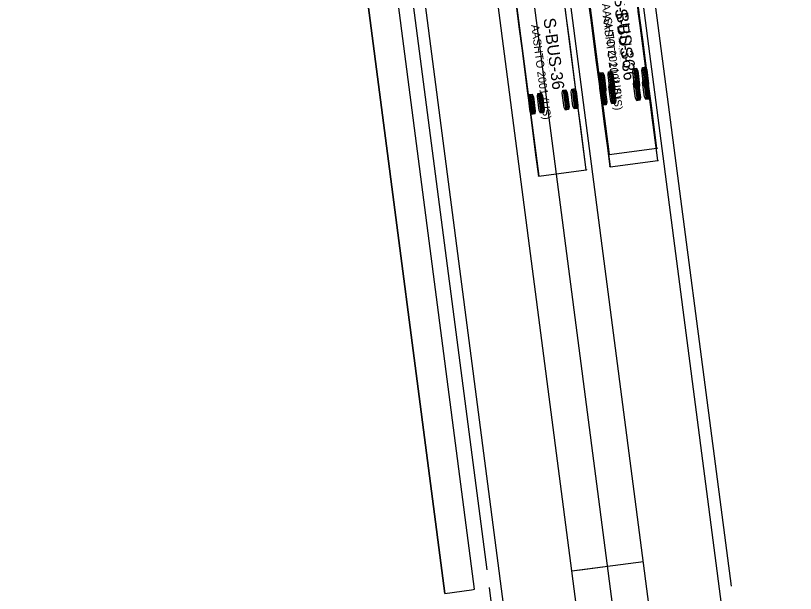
# Model space of a CAD drawing. Extents: x 2367848 to 2369479, y 800728 to 808616.
# Drawn here: x 2368315.2 to 2368445.1, y 807698.4 to 807794.7 of the extents above; entities that cross this region are included whole.
import ezdxf

# ---------------------------------------------------------------- set-up
doc = ezdxf.new("R2010")
doc.units = 0
for name, color, linetype in [('Prop AutoTurn Simulation', 7, 'Continuous'), ('Prop Conc 2ft 6in Curb and Gutter', 7, 'Continuous'), ('Prop Conc 4in Sidewalk', 7, 'Continuous'), ('Prop Conc Drive Radius Type', 7, 'Continuous'), ('Prop Conc Driveway', 7, 'Continuous'), ('Prop Dimension', 7, 'Continuous'), ('Prop EOT', 7, 'Continuous'), ('Prop Horizontal Alignment', 7, 'Continuous'), ('Prop Horizontal Alignment Tick Small', 7, 'Continuous'), ('Prop Lane Lines', 7, 'Continuous'), ('Prop Shade Light', 7, 'Continuous'), ('Scratch_Level_0', 7, 'Continuous')]:
    doc.layers.add(name, color=color, linetype=linetype)

msp = doc.modelspace()

# ---------------------------------------------------------------- linework, layer by layer
at = {"layer": 'Prop AutoTurn Simulation'}
for p, q in [((2368409.64, 807804.99), (2368414.27, 807769.49)), ((2368422.2, 807770.52), (2368417.58, 807806.03)), ((2368410.3, 807768.98), (2368405.68, 807804.48)), ((2368397.74, 807803.44), (2368402.37, 807767.94)), ((2368412.71, 807783.07), (2368413.14, 807779.77)), ((2368412.91, 807783.1), (2368413.35, 807779.79)), ((2368413.12, 807783.12), (2368413.55, 807779.82)), ((2368414.2, 807783.26), (2368414.63, 807779.96)), ((2368414.4, 807783.29), (2368414.83, 807779.99)), ((2368414.61, 807783.32), (2368415.04, 807780.01)), ((2368418.33, 807783.8), (2368418.76, 807780.5)), ((2368418.53, 807783.83), (2368418.96, 807780.52)), ((2368418.74, 807783.86), (2368419.17, 807780.55)), ((2368419.81, 807784), (2368420.25, 807780.69)), ((2368420.02, 807784.02), (2368420.45, 807780.72)), ((2368420.23, 807784.05), (2368420.66, 807780.74)), ((2368401.22, 807781.58), (2368401.65, 807778.27)), ((2368402.3, 807781.72), (2368402.73, 807778.41)), ((2368402.5, 807781.74), (2368402.93, 807778.44)), ((2368402.71, 807781.77), (2368403.14, 807778.46)), ((2368406.43, 807782.25), (2368406.86, 807778.95)), ((2368406.63, 807782.28), (2368407.06, 807778.97)), ((2368406.84, 807782.31), (2368407.27, 807779)), ((2368407.92, 807782.45), (2368408.35, 807779.14)), ((2368408.12, 807782.47), (2368408.55, 807779.17)), ((2368408.33, 807782.5), (2368408.76, 807779.2)), ((2368400.81, 807781.52), (2368401.24, 807778.22)), ((2368401.02, 807781.55), (2368401.45, 807778.24)), ((2368414.27, 807769.49), (2368422.2, 807770.52)), ((2368402.37, 807767.94), (2368410.3, 807768.98))]:
    msp.add_line(p, q, dxfattribs=at)
for points in [[(2368410.3, 807768.98), (2368409.84, 807772.53), (2368409.38, 807776.08), (2368408.91, 807779.63), (2368408.45, 807783.18), (2368407.99, 807786.73), (2368407.53, 807790.28), (2368407.06, 807793.83), (2368406.6, 807797.38)], [(2368414.27, 807769.49), (2368413.8, 807773.04), (2368413.34, 807776.59), (2368412.88, 807780.14), (2368412.42, 807783.69), (2368411.96, 807787.24), (2368411.49, 807790.79), (2368411.03, 807794.34), (2368410.57, 807797.89)], [(2368402.37, 807767.94), (2368401.9, 807771.49), (2368401.44, 807775.04), (2368400.98, 807778.59), (2368400.52, 807782.14), (2368400.06, 807785.69), (2368399.59, 807789.24), (2368399.13, 807792.79), (2368398.67, 807796.34)], [(2368422.2, 807770.52), (2368421.74, 807774.07), (2368421.27, 807777.62), (2368420.81, 807781.17), (2368420.35, 807784.73), (2368419.89, 807788.28), (2368419.43, 807791.83), (2368418.96, 807795.38)]]:
    msp.add_lwpolyline(points, dxfattribs=at)
for points in [[(2368412.66, 807783.06), (2368413.17, 807783.13), (2368413.39, 807782.69), (2368413.7, 807780.31), (2368413.6, 807779.83), (2368413.09, 807779.76), (2368412.87, 807780.2), (2368412.56, 807782.58)], [(2368414.14, 807783.26), (2368414.66, 807783.33), (2368414.88, 807782.88), (2368415.19, 807780.5), (2368415.09, 807780.02), (2368414.57, 807779.95), (2368414.36, 807780.4), (2368414.05, 807782.78)], [(2368418.28, 807783.8), (2368418.79, 807783.86), (2368419.01, 807783.42), (2368419.32, 807781.04), (2368419.22, 807780.56), (2368418.71, 807780.49), (2368418.49, 807780.93), (2368418.18, 807783.31)], [(2368419.76, 807783.99), (2368420.28, 807784.06), (2368420.49, 807783.61), (2368420.8, 807781.23), (2368420.71, 807780.75), (2368420.19, 807780.68), (2368419.98, 807781.13), (2368419.67, 807783.51)], [(2368400.76, 807781.52), (2368401.27, 807781.58), (2368401.49, 807781.14), (2368401.8, 807778.76), (2368401.7, 807778.28), (2368401.19, 807778.21), (2368400.97, 807778.65), (2368400.66, 807781.03)], [(2368402.24, 807781.71), (2368402.76, 807781.78), (2368402.98, 807781.33), (2368403.29, 807778.95), (2368403.19, 807778.47), (2368402.68, 807778.4), (2368402.46, 807778.85), (2368402.15, 807781.23)], [(2368406.38, 807782.25), (2368406.89, 807782.31), (2368407.11, 807781.87), (2368407.42, 807779.49), (2368407.32, 807779.01), (2368406.81, 807778.94), (2368406.59, 807779.38), (2368406.28, 807781.76)], [(2368407.86, 807782.44), (2368408.38, 807782.51), (2368408.6, 807782.07), (2368408.91, 807779.69), (2368408.81, 807779.2), (2368408.29, 807779.14), (2368408.08, 807779.58), (2368407.77, 807781.96)]]:
    msp.add_lwpolyline(points, close=True, dxfattribs=at)
for centre in [(2368422.2, 807770.52), (2368410.3, 807768.98), (2368414.27, 807769.49), (2368402.37, 807767.94)]:
    msp.add_circle(centre, 0.0417, dxfattribs=at)
at = {"layer": 'Prop Conc 2ft 6in Curb and Gutter'}
for p, q in [((2368393.77, 807702.32), (2368371.39, 807874.22)), ((2368434.46, 807699.56), (2368421.24, 807801.1))]:
    msp.add_line(p, q, dxfattribs=at)
at = {"layer": 'Prop Conc 4in Sidewalk'}
for p, q in [((2368391.67, 807699.07), (2368368.91, 807873.9)), ((2368386.72, 807698.38), (2368363.95, 807873.25))]:
    msp.add_line(p, q, dxfattribs=at)
msp.add_arc((2368390.79, 807701.94), 3, 277.4416, 287.0385, dxfattribs=at)
at = {"layer": 'Prop Conc Drive Radius Type'}
msp.add_line((2368396.22, 807683.48), (2368394.15, 807699.35), dxfattribs=at)
at = {"layer": 'Prop Conc Driveway'}
msp.add_line((2368386.72, 807698.38), (2368391.18, 807698.96), dxfattribs=at)
at = {"layer": 'Prop Dimension'}
msp.add_line((2368419.81, 807703.64), (2368407.91, 807702.09), dxfattribs=at)
at = {"layer": 'Prop EOT'}
for p, q in [((2368445.12, 807602.21), (2368408.77, 807881.38)), ((2368409.42, 807597.56), (2368373.37, 807874.48))]:
    msp.add_line(p, q, dxfattribs=at)
at = {"layer": 'Prop Horizontal Alignment'}
msp.add_line((2368427.27, 807599.89), (2368315.24, 808460.34), dxfattribs=at)
at = {"layer": 'Prop Horizontal Alignment Tick Small'}
msp.add_line((2368413.86, 807702.87), (2368408.91, 807702.22), dxfattribs=at)
at = {"layer": 'Prop Lane Lines'}
for p, q in [((2368433.22, 807600.66), (2368406.9, 807802.81)), ((2368421.32, 807599.11), (2368395, 807801.26))]:
    msp.add_line(p, q, dxfattribs=at)
at = {"layer": 'Prop Shade Light'}
for p, q in [((2368391.67, 807699.07), (2368368.91, 807873.9)), ((2368363.95, 807873.25), (2368386.72, 807698.38)), ((2368386.72, 807698.38), (2368391.18, 807698.96))]:
    msp.add_line(p, q, dxfattribs=at)
msp.add_arc((2368390.79, 807701.94), 3, 277.4416, 287.0385, dxfattribs=at)
at = {"layer": 'Scratch_Level_0'}
for p, q in [((2368422.06, 807772.57), (2368417.44, 807808.07)), ((2368409.51, 807807.04), (2368414.13, 807771.54)), ((2368418.19, 807785.85), (2368418.62, 807782.55)), ((2368418.4, 807785.88), (2368418.83, 807782.57)), ((2368418.6, 807785.91), (2368419.03, 807782.6)), ((2368419.68, 807786.05), (2368420.11, 807782.74)), ((2368419.88, 807786.07), (2368420.32, 807782.77)), ((2368420.09, 807786.1), (2368420.52, 807782.79)), ((2368412.57, 807785.12), (2368413, 807781.81)), ((2368412.78, 807785.15), (2368413.21, 807781.84)), ((2368412.98, 807785.17), (2368413.42, 807781.87)), ((2368414.06, 807785.31), (2368414.49, 807782.01)), ((2368414.27, 807785.34), (2368414.7, 807782.03)), ((2368414.47, 807785.37), (2368414.9, 807782.06)), ((2368414.13, 807771.54), (2368422.06, 807772.57))]:
    msp.add_line(p, q, dxfattribs=at)
for points in [[(2368422.06, 807772.57), (2368421.6, 807776.12), (2368421.14, 807779.67), (2368420.68, 807783.22), (2368420.21, 807786.77), (2368419.75, 807790.32), (2368419.29, 807793.87), (2368418.83, 807797.42)], [(2368414.13, 807771.54), (2368413.67, 807775.09), (2368413.2, 807778.64), (2368412.74, 807782.19), (2368412.28, 807785.74), (2368411.82, 807789.29), (2368411.36, 807792.84), (2368410.89, 807796.39)]]:
    msp.add_lwpolyline(points, dxfattribs=at)
for points in [[(2368418.14, 807785.84), (2368418.66, 807785.91), (2368418.87, 807785.47), (2368419.18, 807783.09), (2368419.09, 807782.61), (2368418.57, 807782.54), (2368418.35, 807782.98), (2368418.04, 807785.36)], [(2368419.63, 807786.04), (2368420.14, 807786.11), (2368420.36, 807785.66), (2368420.67, 807783.28), (2368420.57, 807782.8), (2368420.06, 807782.73), (2368419.84, 807783.18), (2368419.53, 807785.56)], [(2368412.52, 807785.11), (2368413.04, 807785.18), (2368413.25, 807784.74), (2368413.56, 807782.36), (2368413.47, 807781.87), (2368412.95, 807781.81), (2368412.74, 807782.25), (2368412.43, 807784.63)], [(2368414.01, 807785.31), (2368414.52, 807785.37), (2368414.74, 807784.93), (2368415.05, 807782.55), (2368414.95, 807782.07), (2368414.44, 807782), (2368414.22, 807782.44), (2368413.91, 807784.82)]]:
    msp.add_lwpolyline(points, close=True, dxfattribs=at)
for centre in [(2368422.06, 807772.57), (2368414.13, 807771.54)]:
    msp.add_circle(centre, 0.0417, dxfattribs=at)

# ---------------------------------------------------------------- texts
at = {"layer": 'Prop AutoTurn Simulation'}
for s, height, p in [('AASHTO 2001 (US)', 1.3333, (2368413, 807794.65)), ('S-BUS-36', 2, (2368415.05, 807795.71)), ('S-BUS-36', 2, (2368403.15, 807794.16)), ('AASHTO 2001 (US)', 1.3333, (2368401.1, 807793.1)), ('(c) 2014 Transoft Solutions, Inc. All rights reserved.', 0.08, (2368415.67, 807789.37)), ('(c) 2014 Transoft Solutions, Inc. All rights reserved.', 0.08, (2368403.77, 807787.82))]:
    msp.add_text(s, height=height, rotation=277.418, dxfattribs=at).set_placement(p)
at = {"layer": 'Scratch_Level_0'}
for s, height, p in [('S-BUS-36', 2, (2368414.91, 807797.76)), ('AASHTO 2011 (US)', 1.3333, (2368412.88, 807796.61)), ('(c) 2016 Transoft Solutions, Inc. All rights reserved.', 0.08, (2368415.53, 807791.42))]:
    msp.add_text(s, height=height, rotation=277.418, dxfattribs=at).set_placement(p)

doc.saveas('drawing.dxf')
